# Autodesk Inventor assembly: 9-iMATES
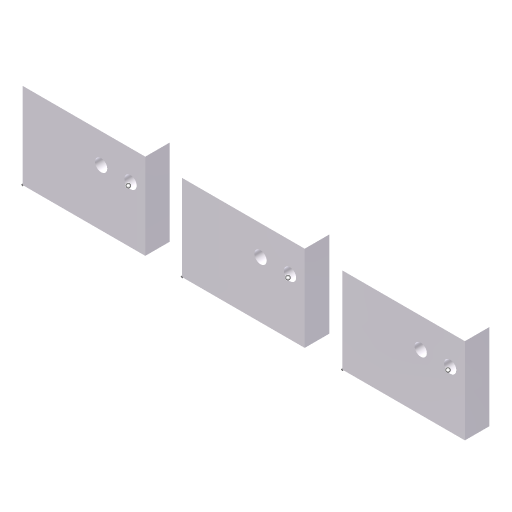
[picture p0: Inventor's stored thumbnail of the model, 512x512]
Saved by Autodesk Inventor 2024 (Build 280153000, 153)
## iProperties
Created: 2023-03
Part Number: 9-iMATES
Document SubType Name: Assembly
Designer: Andrzej Jaskulski
Manufacturer: Standard
Standards Organization: Custom
Checked By: A.J.
Engr Approved By: Andrzej Jaskulski
Mfg Approved By: Andrzej Jaskulski
Authority: A.J.
Company: ATC
Title: A.J.: Kurs R2024-MEP
Author: Andrzej Jaskulski
Revision Number: 1/24
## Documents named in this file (2)
- C:\Users\AndJas\Documents\R2024-MEP\Obszar roboczy\9-iMATES.iam
- C:\Users\AndJas\Documents\R2024-MEP\Obszar roboczy\9-iMATE-BAZA.ipt
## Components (3 placed, 1 different names)
1. 9-iMATE-BAZA:1
2. 9-iMATE-BAZA:2
3. 9-iMATE-BAZA:3
